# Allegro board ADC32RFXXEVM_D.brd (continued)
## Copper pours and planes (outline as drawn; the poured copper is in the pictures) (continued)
N19887760 on TOP: 84.02,60.77 84.02,58.81 84.98,58.81 84.98,60.77
N19887762 on TOP: 83.97,52.1 83.97,54.05 85.04,54.05 85.04,52.1
N19887836 on TOP: 75.9,61.42 75.9,62.33 76.89,63.32 76.89,64.06 77.93,64.06 77.93,63.02 78.13,62.81 78.13,61.42
N19887836 on L6_PWR: 75.56,62.87 75.56,52.07 80.64,52.07 80.64,62.87
N19887910 on TOP: 73.84,56.29 73.84,55.02 75.79,55.02 75.79,56.29
N19887912 on TOP: 73.61,54.38 73.61,53.16 75.69,53.16 75.69,54.38
N19887930 on TOP: 73.86,58.55 73.86,57.28 75.82,57.28 75.82,58.55
N20113513 on BOTTOM: 72.95,9.17 72.95,11.07 73.96,11.07 73.96,13.49 80.06,13.49 80.06,11.71 77.52,9.17
N20114896 on TOP: 85.12,15.82 85.12,9.47 89.05,9.47 89.05,15.82
N20114896 on BOTTOM: 83.46,5.66 83.46,14.55 84.73,15.82 88.67,15.82 89.05,15.44 89.05,6.55 87.15,4.65 84.48,4.65
N20121078 on BOTTOM: 78.41,14.25 78.41,16.03 77.52,16.92 74.09,16.92 74.09,18.95 78.79,18.95 80.7,17.04 80.7,14.25
N20220794 on TOP: 94.36,18.67 94.36,15.75 102.23,15.75 102.23,18.67
N20220794 on BOTTOM: 94.36,18.67 96.9,18.67 96.9,10.67 93.22,10.67 93.22,12.45 94.36,13.59

Small or netless copper shapes (teardrops, artwork), in the pictures only: 2 on TOP

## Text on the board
BOTTOM: LAYER 8 (BOTTOM SIDE)
Board Geometry/Soldermask Bottom: SOLDERMASK BOTTOM
Ref Des/Silkscreen Bottom: SILKSCREEN BOTTOM
User.Comments: R57 | R177 | R178 | R184 | R175 | R176 | R179 | C400 | C410 | C409 | R59 | R58 | C403 | R192 | R187 | R191 | C412 | C413 | C432 | C431 | R189 | A1 | B1 | C1 | D1 | E1 | F1 | G1 | H1 | J1 | K1 | K36 | A40 | B40 | C40 | D40 | E40 | F40 | G40 | H40 | J40 | K40 | A6 | A11 | A16 | A21 | A26 | A31 | A36 | K6 | K11 | K16 | K21 | K26 | K31 | * | C157 | C158 | C156 | R152 | R151 | R85 | R84 | R87 | R86 | U30 | C389 | C388 | C170 | C171 | C385 | R53 | R52 | R51 | R180 | R50 | R67 | R181 | R70 | R68 | R69 | R63 | R47 | C70 | C74 | C73 | R64 | T6 | R56 | C394 | R174 | R182 | R186 | R183 | C420 | C188 | C187 | C186 | C185 | R185 | C28 | R75 | R79 | R164 | C67 | C69 | R48 | R49 | C419 | C418 | R66 | R65 | C75 | R55 | R60 | C395 | C421 | C47 | C45 | C44 | C428 | R165 | C8 | C9 | C38 | C39 | R188 | Y1 | U17 | U29 | U15 | J5 | U12 | C163 | C160 | C162 | C161 | C159 | R80 | R72 | C84 | C81 | R54 | U31 | C71 | C85 | C82 | U3 | R159 | R141 | R138 | R139 | R140 | R137 | C191 | U16 | C190 | C189 | C60 | C59 | C58 | U5 | HS1 | T5 | J11 | R35 | R33 | FB16 | R81 | R73 | R71 | R76 | R82 | R74 | C72 | C83 | C86 | C386 | R158 | R145 | C193 | R143 | FB17 | C198 | C173 | R32 | R31 | R34 | R95 | FB12 | C103 | C104 | C197 | C194 | C195 | C196 | C122 | C126 | R157 | R133 | R77 | R78 | R40 | ADC CLK | INSTALL HEATSINK HS1 | ON BOTTOM SIDE OF BOARD | J10 | TEXAS INSTRUMENTS, INC. | PCB REV D | ADC32RFXXEVM | 8MIL TRACE WIDTH AND 6MIL SPACING ON BOTTOM SIDE OF BOARD SHALL BE 100 OHMS DIFFERENTIAL +/- 10%. | TOP VIEW | BOTTOM VIEW
TOP: LAYER 1 (TOP SIDE)
Board Geometry/Soldermask Top: SOLDERMASK TOP
Ref Des/Silkscreen Top: CLK | EXT | ADC CLK IN | J5 | LMK SYNC | UL94V-0 | LOCKED | PCB REV D | ADC32RF80 EVM | ADC32RF   EVM | ADC32RF45 EVM | SILKSCREEN TOP
L2_GND: LAYER 2 - GND
L3_PWR: LAYER 3 - POWER
L4_SIG: LAYER 4 - GND
L5_GND: LAYER 5 - GND
L6_PWR: LAYER 6 - POWER/SIGNAL
L7_GND: LAYER 7 - GROUND
PLACE_BOUND_TOP: PASTEMASK TOP
DEVICE_TYPE_BOTTOM: PASTEMASK BOTTOM
USER_PART_NUM_BOTTOM: SOLDERMASK TOP SOCKET BOARD
PAGE_OUTLINE: PASTEMASK TOP SOCKET BOARD
User.11: 0.25oz / Plate to 0.5oz min Layer 6 | R-1775V | R-1650V | Core 0.008" | Copper Foil | Core 0.012" | Pre-preg 0.0042 | 0.5oz / 0.5oz Layer 5 & 6 | (material) | LAYER 7 | LAYER 8
User.12: 10-18-15 | 3. MARK BOARD'S SILKSCREEN WITH THE APPROPRIATE EVM PART NUMBER. | 4. IPC-A-610 / ACCEPTABILITY OF ELECTRONIC ASSEMBLIES, CLASS2, CURRENT REVISION.
User.21: FIGURE | SIZE | 6.0 | 8.0 | 10.0 | 12.0 | 13.0 | 15.0 | 38.0 | 40.0 | 62.0 | 67.0 | 106.0 | 120.0 | 125.0 | 140.0 | 35.0 | 50.0 | DRILL CHART: TOP to BOTTOM | ALL UNITS ARE IN MILS | PLATED | NON-PLATED | QTY | 169 | 2223 | 49 | 479 | 16 | 8 | 19 | 5 | 12 | 2 | 1
